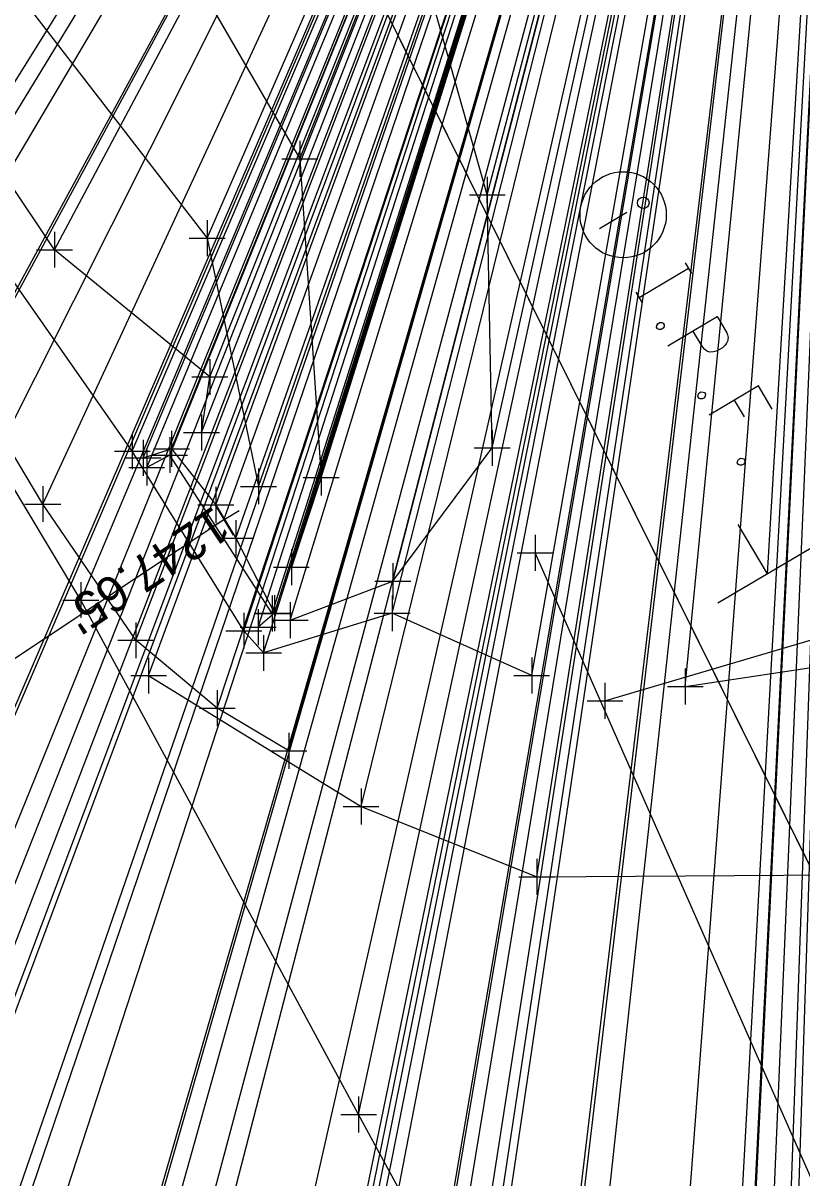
# Model space of a CAD drawing. Extents: x 125846 to 132549, y 511012 to 513420.
# Drawn here: x 126944.67 to 126966.37, y 512252.39 to 512284.55 of the extents above; entities that cross this region are included whole.
import ezdxf

# ---------------------------------------------------------------- set-up
doc = ezdxf.new("R2010")
doc.units = 0
for name, color, linetype in [('Default', 7, 'Continuous'), ('DR_X_Ditch', 7, 'Continuous'), ('DR_X_Elev_Flow', 7, 'Continuous'), ('DR_X_Headwall', 7, 'Continuous'), ('DR_X_Storm_Sewer', 7, 'Continuous'), ('DT_X_Void', 7, 'Continuous'), ('PV_X_EOP', 7, 'Continuous'), ('PV_X_Shoulder_Aggregate', 7, 'Continuous'), ('SC_Scratch1', 7, 'Continuous'), ('SV_Observation', 7, 'Continuous'), ('SV_X_Break_Lines', 7, 'Continuous'), ('SV_X_Mon_Cells_Found', 7, 'Continuous'), ('UT_X_Electric', 7, 'Continuous'), ('UT_X_Overhead_Cable_TV', 7, 'Continuous'), ('UT_X_Overhead_Telecom', 7, 'Continuous'), ('UT_X_Sanitary_Line', 7, 'Continuous'), ('UT_X_Water', 7, 'Continuous')]:
    doc.layers.add(name, color=color, linetype=linetype)

msp = doc.modelspace()

# ---------------------------------------------------------------- linework, layer by layer
at = {"layer": 'Default'}
msp.add_lwpolyline([(126950.265, 512270.713), (126896.037, 512234.72)], dxfattribs=at)
at = {"layer": 'DR_X_Ditch'}
msp.add_lwpolyline([(126931.779, 512302.404), (126940.271, 512290.881), (126949.8, 512278.561), (126951.232, 512271.647)], dxfattribs=at)
at = {"layer": 'DR_X_Elev_Flow'}
for p, q in [((126950.01, 512271.143), (126950.521, 512270.284)), ((126950.695, 512270.969), (126949.836, 512270.458)), ((126950.265, 512270.713), (126950.265, 512270.713))]:
    msp.add_line(p, q, dxfattribs=at)
at = {"layer": 'DR_X_Headwall'}
msp.add_lwpolyline([(126951.61, 512268.109), (126948.755, 512272.52), (126948.114, 512272.169)], dxfattribs=at)
at = {"layer": 'DR_X_Storm_Sewer'}
msp.add_line((126950.265, 512270.713), (126896.037, 512234.72), dxfattribs=at)
at = {"layer": 'DT_X_Void'}
for p, q in [((126965.407, 512269.208), (126964.591, 512270.585)), ((126966.783, 512270.023), (126964.03, 512268.393))]:
    msp.add_line(p, q, dxfattribs=at)
at = {"layer": 'PV_X_EOP'}
for points in [[(127037.881, 512019.282), (127029.702, 512062.957), (127023.055, 512092.199), (127012.397, 512127.764), (127009.4, 512137.026), (126996.87, 512167.973), (126984.43, 512195.874), (126972.834, 512218.045), (126964.85, 512234.205), (126954.019, 512254.154), (126946.281, 512268.482), (126939.955, 512279.025), (126918.506, 512314.814), (126894.741, 512355.014), (126873.069, 512391.797), (126850.03, 512430.621), (126826.944, 512469.558), (126798.525, 512517.081)], [(126948.169, 512266.375), (126954.086, 512262.732), (126958.983, 512260.769), (126976.878, 512260.89), (126992.803, 512261.723), (127036.537, 512268.503), (127075.764, 512272.255), (127127.269, 512276.447), (127167.29, 512279.583), (127210.087, 512281.645)]]:
    msp.add_lwpolyline(points, dxfattribs=at)
at = {"layer": 'PV_X_Shoulder_Aggregate'}
for points in [[(126958.84, 512266.377), (126954.951, 512268.112), (126951.372, 512267.006), (126950.82, 512267.628), (126947.713, 512272.624), (126942.585, 512279.945), (126923.264, 512313.488), (126899.243, 512358.525), (126887.065, 512383.388), (126879.438, 512396.236), (126854.348, 512434.479), (126831.718, 512472.742), (126803.298, 512520.892), (126783.272, 512554.618), (126752.52, 512603.425), (126737.929, 512626.869), (126732.302, 512635.669), (126721.039, 512651.897), (126710.1, 512670.464), (126691.089, 512704.83), (126677.851, 512725.452), (126654.698, 512768.66), (126631.692, 512807.538)], [(126963.12, 512266.076), (126970.887, 512267.241), (126992.233, 512266.344), (127035.738, 512274.804), (127075.146, 512275.986), (127126.704, 512282.468), (127166.378, 512286.376), (127210.227, 512288.359)]]:
    msp.add_lwpolyline(points, dxfattribs=at)
at = {"layer": 'SV_Observation'}
for p in [(126910.197, 512205.448), (126916.338, 512235.986), (126917.023, 512234.293), (126918.827, 512229.844), (126920.774, 512181.176), (126924.495, 512219.182), (126924.649, 512210.571), (126925.866, 512221.959), (126928.334, 512198.193), (126928.781, 512223.572), (126929.516, 512186.215), (126929.641, 512186.12), (126932.051, 512224.53), (126932.369, 512224.671), (126933.25, 512195.561), (126933.25, 512195.561), (126933.25, 512195.561), (126933.25, 512195.561), (126935.039, 512195.893), (126935.796, 512226.683), (126936.277, 512196.757), (126938.255, 512168.68), (126938.806, 512190.388), (126938.974, 512147.487), (126939.361, 512245.706), (126939.361, 512245.706), (126939.719, 512136.206), (126939.761, 512268.268), (126940.113, 512181.812), (126941.131, 512179.586), (126941.547, 512187.262), (126942.585, 512279.945), (126945.221, 512271.156), (126945.547, 512278.24), (126946.04, 512189.834), (126946.281, 512268.482), (126946.606, 512119.085), (126947.627, 512144.927), (126947.713, 512272.624), (126947.719, 512194.841), (126947.808, 512267.36), (126948.02, 512272.439), (126948.114, 512272.169), (126948.169, 512266.375), (126948.755, 512272.52), (126948.807, 512272.69), (126948.869, 512191.352), (126949.168, 512227.353), (126949.325, 512191.546), (126949.643, 512273.145), (126949.8, 512278.561), (126949.872, 512274.694), (126950.042, 512271.131), (126950.081, 512265.469), (126950.265, 512270.713), (126950.599, 512270.205), (126950.82, 512267.628), (126951.219, 512267.727), (126951.232, 512271.647), (126951.372, 512267.006), (126951.61, 512268.109), (126951.673, 512268.115), (126952.076, 512264.281), (126952.11, 512267.918), (126952.145, 512269.395), (126952.378, 512280.771), (126952.974, 512271.891), (126953.188, 512193.545), (126954.019, 512254.154), (126954.086, 512262.732), (126954.951, 512268.112), (126954.974, 512269.005), (126955.548, 512150.693), (126957.39, 512096.524), (126957.529, 512121.259), (126957.604, 512279.767), (126957.738, 512272.717), (126958.84, 512266.377), (126958.983, 512260.769), (126960.055, 512151.814), (126963.12, 512266.076), (126964.163, 512198.205), (126964.163, 512198.205), (126964.85, 512234.205), (126965.407, 512269.208), (126965.733, 512234.875)]:
    msp.add_line(p, (126968.531, 512321.464), dxfattribs=at)
at = {"layer": 'SV_X_Break_Lines'}
for points in [[(126952.076, 512264.281), (126950.081, 512265.469), (126947.808, 512267.36), (126945.221, 512271.156), (126940.389, 512279.25), (126918.895, 512315.137)], [(126952.11, 512267.918), (126954.974, 512269.005), (126957.738, 512272.717), (126957.604, 512279.767), (126954.442, 512290.954), (126943.364, 512299.535), (126933.579, 512304.648)], [(126939.199, 512296.922), (126946.813, 512290.382), (126952.378, 512280.771), (126952.974, 512271.891), (126952.145, 512269.395)], [(126949.643, 512273.145), (126949.872, 512274.694), (126945.547, 512278.24), (126939.043, 512287.961)], [(126948.02, 512272.439), (126948.807, 512272.69), (126950.042, 512271.131), (126950.599, 512270.205), (126951.673, 512268.115), (126951.219, 512267.727)]]:
    msp.add_lwpolyline(points, dxfattribs=at)
at = {"layer": 'SV_X_Mon_Cells_Found'}
msp.add_line((126961.489, 512279.272), (126960.73, 512278.821), dxfattribs=at)
for points in [[(126963.115, 512277.877), (126963.295, 512277.574)], [(126961.83, 512276.907), (126963.205, 512277.725)], [(126961.739, 512277.059), (126961.92, 512276.755)], [(126962.63, 512275.562), (126964.005, 512276.38), (126964.276, 512275.925), (126964.293, 512275.871), (126964.311, 512275.792), (126964.306, 512275.751), (126964.301, 512275.71), (126964.27, 512275.639), (126964.232, 512275.579), (126964.157, 512275.508), (126964.027, 512275.431), (126963.978, 512275.415), (126963.902, 512275.395), (126963.804, 512275.388), (126963.749, 512275.406), (126963.71, 512275.422), (126963.66, 512275.456), (126963.604, 512275.526), (126963.334, 512275.981)], [(126962.504, 512276.192), (126962.532, 512276.145), (126962.528, 512276.104), (126962.501, 512276.05), (126962.447, 512276.017), (126962.387, 512276.02), (126962.348, 512276.035), (126962.32, 512276.083), (126962.325, 512276.124), (126962.351, 512276.178), (126962.405, 512276.211), (126962.466, 512276.208), (126962.504, 512276.192)], [(126965.544, 512273.794), (126965.155, 512274.447), (126963.78, 512273.629)], [(126963.654, 512274.26), (126963.682, 512274.212), (126963.677, 512274.171), (126963.651, 512274.117), (126963.597, 512274.085), (126963.537, 512274.087), (126963.498, 512274.103), (126963.47, 512274.15), (126963.474, 512274.192), (126963.501, 512274.246), (126963.555, 512274.278), (126963.615, 512274.275), (126963.654, 512274.26)], [(126964.484, 512274.048), (126964.76, 512273.584)], [(126964.753, 512272.413), (126964.781, 512272.365), (126964.776, 512272.324), (126964.75, 512272.27), (126964.696, 512272.238), (126964.636, 512272.24), (126964.597, 512272.256), (126964.569, 512272.303), (126964.573, 512272.344), (126964.6, 512272.399), (126964.654, 512272.431), (126964.714, 512272.428), (126964.753, 512272.413)]]:
    msp.add_lwpolyline(points, dxfattribs=at)
for centre, radius in [((126961.389, 512279.212), 1.2), ((126961.949, 512279.546), 0.16)]:
    msp.add_circle(centre, radius, dxfattribs=at)
at = {"layer": 'UT_X_Electric'}
msp.add_lwpolyline([(126951.927, 512290.638), (126995.9, 512201.988)], dxfattribs=at)
at = {"layer": 'UT_X_Overhead_Cable_TV'}
msp.add_lwpolyline([(127151.135, 511501.172), (127120.309, 511642.52), (127100.367, 511762.141), (127071.139, 511920.25), (127038.245, 512070.716), (126995.9, 512201.988), (126951.927, 512290.638), (126888.078, 512393.934), (126821.569, 512508.62), (126750.649, 512627.876), (126677.44, 512750.383), (126606.516, 512869.514), (126525.52, 513001.821), (126518.89, 513012.818), (126445.697, 513128.427), (126355.465, 513218.249), (126225.896, 513304.994), (126163.086, 513330.602), (126019.813, 513381.694)], dxfattribs=at)
at = {"layer": 'UT_X_Overhead_Telecom'}
msp.add_lwpolyline([(127151.135, 511501.172), (127120.309, 511642.52), (127100.367, 511762.141), (127071.139, 511920.25), (127038.245, 512070.716), (126995.9, 512201.988), (126951.927, 512290.638), (126888.078, 512393.934), (126821.569, 512508.62), (126750.649, 512627.876), (126677.44, 512750.383), (126606.516, 512869.514), (126525.52, 513001.821), (126518.89, 513012.818), (126445.697, 513128.427), (126354.464, 513218.752), (126225.896, 513304.994), (126163.086, 513330.602), (126019.813, 513381.694)], dxfattribs=at)
at = {"layer": 'UT_X_Sanitary_Line'}
for p, q in [((126952.378, 512281.271), (126952.378, 512280.271)), ((126951.878, 512280.771), (126952.878, 512280.771)), ((126952.378, 512280.771), (126952.378, 512280.771)), ((126957.604, 512280.267), (126957.604, 512279.267)), ((126957.104, 512279.767), (126958.104, 512279.767)), ((126957.604, 512279.767), (126957.604, 512279.767)), ((126949.8, 512279.061), (126949.8, 512278.061)), ((126945.547, 512278.74), (126945.547, 512277.74)), ((126949.3, 512278.561), (126950.3, 512278.561)), ((126949.8, 512278.561), (126949.8, 512278.561)), ((126945.047, 512278.24), (126946.047, 512278.24)), ((126945.547, 512278.24), (126945.547, 512278.24)), ((126949.872, 512275.194), (126949.872, 512274.194)), ((126949.372, 512274.694), (126950.372, 512274.694)), ((126949.872, 512274.694), (126949.872, 512274.694)), ((126949.643, 512273.645), (126949.643, 512272.645)), ((126947.713, 512273.124), (126947.713, 512272.124)), ((126948.755, 512273.02), (126948.755, 512272.02)), ((126948.807, 512273.19), (126948.807, 512272.19)), ((126949.143, 512273.145), (126950.143, 512273.145)), ((126949.643, 512273.145), (126949.643, 512273.145)), ((126957.738, 512273.217), (126957.738, 512272.217)), ((126948.02, 512272.939), (126948.02, 512271.939)), ((126957.238, 512272.717), (126958.238, 512272.717)), ((126957.738, 512272.717), (126957.738, 512272.717)), ((126947.213, 512272.624), (126948.213, 512272.624)), ((126947.52, 512272.439), (126948.52, 512272.439)), ((126947.713, 512272.624), (126947.713, 512272.624)), ((126948.02, 512272.439), (126948.02, 512272.439)), ((126948.114, 512272.669), (126948.114, 512271.669)), ((126948.255, 512272.52), (126949.255, 512272.52)), ((126948.307, 512272.69), (126949.307, 512272.69)), ((126948.755, 512272.52), (126948.755, 512272.52)), ((126948.807, 512272.69), (126948.807, 512272.69)), ((126952.974, 512272.391), (126952.974, 512271.391)), ((126947.614, 512272.169), (126948.614, 512272.169)), ((126948.114, 512272.169), (126948.114, 512272.169)), ((126951.232, 512272.147), (126951.232, 512271.147)), ((126952.474, 512271.891), (126953.474, 512271.891)), ((126952.974, 512271.891), (126952.974, 512271.891)), ((126945.221, 512271.656), (126945.221, 512270.656)), ((126950.042, 512271.631), (126950.042, 512270.631)), ((126950.732, 512271.647), (126951.732, 512271.647)), ((126951.232, 512271.647), (126951.232, 512271.647)), ((126944.721, 512271.156), (126945.721, 512271.156)), ((126945.221, 512271.156), (126945.221, 512271.156)), ((126949.542, 512271.131), (126950.542, 512271.131)), ((126950.042, 512271.131), (126950.042, 512271.131)), ((126950.599, 512270.705), (126950.599, 512269.705)), ((126950.099, 512270.205), (126951.099, 512270.205)), ((126950.599, 512270.205), (126950.599, 512270.205)), ((126958.939, 512270.295), (126958.939, 512269.295)), ((126952.145, 512269.895), (126952.145, 512268.895)), ((126954.974, 512269.505), (126954.974, 512268.505)), ((126958.439, 512269.795), (126959.439, 512269.795)), ((126958.939, 512269.795), (126958.939, 512269.795)), ((126951.645, 512269.395), (126952.645, 512269.395)), ((126952.145, 512269.395), (126952.145, 512269.395)), ((126946.281, 512268.982), (126946.281, 512267.982)), ((126954.474, 512269.005), (126955.474, 512269.005)), ((126954.974, 512269.005), (126954.974, 512269.005)), ((126951.61, 512268.609), (126951.61, 512267.609)), ((126951.673, 512268.615), (126951.673, 512267.615)), ((126954.951, 512268.612), (126954.951, 512267.612)), ((126945.781, 512268.482), (126946.781, 512268.482)), ((126946.281, 512268.482), (126946.281, 512268.482)), ((126951.219, 512268.227), (126951.219, 512267.227)), ((126952.11, 512268.418), (126952.11, 512267.418)), ((126950.82, 512268.128), (126950.82, 512267.128)), ((126951.11, 512268.109), (126952.11, 512268.109)), ((126951.173, 512268.115), (126952.173, 512268.115)), ((126951.61, 512268.109), (126951.61, 512268.109)), ((126951.61, 512267.918), (126952.61, 512267.918)), ((126951.673, 512268.115), (126951.673, 512268.115)), ((126952.11, 512267.918), (126952.11, 512267.918)), ((126954.451, 512268.112), (126955.451, 512268.112)), ((126954.951, 512268.112), (126954.951, 512268.112)), ((126947.808, 512267.86), (126947.808, 512266.86)), ((126950.32, 512267.628), (126951.32, 512267.628)), ((126950.719, 512267.727), (126951.719, 512267.727)), ((126950.82, 512267.628), (126950.82, 512267.628)), ((126951.219, 512267.727), (126951.219, 512267.727)), ((126947.308, 512267.36), (126948.308, 512267.36)), ((126947.808, 512267.36), (126947.808, 512267.36)), ((126951.372, 512267.506), (126951.372, 512266.506)), ((126950.872, 512267.006), (126951.872, 512267.006)), ((126951.372, 512267.006), (126951.372, 512267.006)), ((126948.169, 512266.875), (126948.169, 512265.875)), ((126958.84, 512266.877), (126958.84, 512265.877)), ((126947.669, 512266.375), (126948.669, 512266.375)), ((126948.169, 512266.375), (126948.169, 512266.375)), ((126958.34, 512266.377), (126959.34, 512266.377)), ((126958.84, 512266.377), (126958.84, 512266.377)), ((126963.12, 512266.576), (126963.12, 512265.576)), ((126950.081, 512265.969), (126950.081, 512264.969)), ((126960.882, 512266.175), (126960.882, 512265.175)), ((126962.62, 512266.076), (126963.62, 512266.076)), ((126963.12, 512266.076), (126963.12, 512266.076)), ((126960.382, 512265.675), (126961.382, 512265.675)), ((126960.882, 512265.675), (126960.882, 512265.675)), ((126949.581, 512265.469), (126950.581, 512265.469)), ((126950.081, 512265.469), (126950.081, 512265.469)), ((126952.076, 512264.781), (126952.076, 512263.781)), ((126951.576, 512264.281), (126952.576, 512264.281)), ((126952.076, 512264.281), (126952.076, 512264.281)), ((126954.086, 512263.232), (126954.086, 512262.232)), ((126953.586, 512262.732), (126954.586, 512262.732)), ((126954.086, 512262.732), (126954.086, 512262.732)), ((126958.983, 512261.269), (126958.983, 512260.269)), ((126958.483, 512260.769), (126959.483, 512260.769)), ((126958.983, 512260.769), (126958.983, 512260.769)), ((126954.019, 512254.654), (126954.019, 512253.654)), ((126953.519, 512254.154), (126954.519, 512254.154)), ((126954.019, 512254.154), (126954.019, 512254.154))]:
    msp.add_line(p, q, dxfattribs=at)
at = {"layer": 'UT_X_Water'}
for points in [[(126960.882, 512265.675), (126978.876, 512270.986), (126998.972, 512275.477)], [(127120.897, 511538.029), (127108.138, 511584.202), (127099.503, 511621.164), (127090.048, 511669.514), (127082.171, 511717.385), (127073.574, 511775.056), (127066.81, 511829.446), (127058.814, 511888.602), (127043.406, 511993.442), (127034.289, 512050.048), (127018.031, 512117.781), (127000.658, 512166.916), (126987.6, 512201.022), (126978.137, 512226.33), (126958.939, 512269.795)]]:
    msp.add_lwpolyline(points, dxfattribs=at)

# ---------------------------------------------------------------- texts
at = {"layer": 'SC_Scratch1'}
msp.add_text("1247.65'", height=1, rotation=213.574, dxfattribs=at).set_placement((126949.989, 512271.13))

doc.saveas('drawing.dxf')
